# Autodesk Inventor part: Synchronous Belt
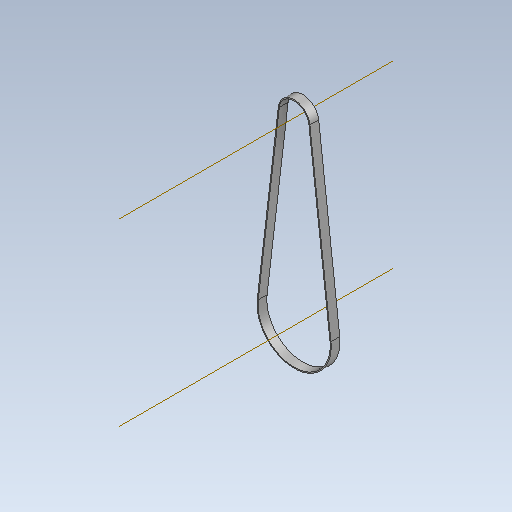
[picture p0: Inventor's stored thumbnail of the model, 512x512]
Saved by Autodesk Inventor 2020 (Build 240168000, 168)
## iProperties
CustomPartVersion: 1
Created: 2019-09
Part Number: Synchronous Belt
Material: Rubber
Document SubType Name: Modeling
Designer: user
Density: 0.93 g/cm^3
Appearance: Rubber - Black - Version 1.1
Mass: 4.97631 g
Surface Area: 116.719 cm^2
Volume: 5.35087 cm^3
Author: user
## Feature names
1. Belt
## Parameters: da_B = 9.398 mm, da_pb = 5.08 mm, da_L = 558.8 mm, da_a = 0.254 mm, da_S = 2.5654 mm, da_Beta = 25 deg, da_Ht = 1.27 mm, d0 = 9.398 mm, d2 = 0, da_H = 2.286 mm, d4 = 0.254 mm, da_a2 = 0.762 mm, d5 = 0.762 mm, d6 = 0, d7 = 0, d8 = 0, d9 = 0, d10 = 0, d11 = 0
